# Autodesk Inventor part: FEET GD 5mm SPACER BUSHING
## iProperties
Created: 2007-03
Part Number: FEET GD 5mm SPACER BUSHING
Material: Steel
Document SubType Name: Modeling
Designer: Andy Moles
Mass: 1.7633 g
Surface Area: 4.90088 cm^2
Volume: 0.224624 cm^3
Density: 7.85 g/cm^3
Author: Andy Moles
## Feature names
1. Extrusion1
